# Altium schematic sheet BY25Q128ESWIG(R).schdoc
size 127 x 101 mm
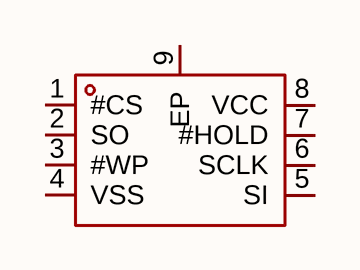
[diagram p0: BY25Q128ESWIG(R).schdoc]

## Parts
U?  by25q128eswig(r)  [DFN-8_L6.0-W5.0-P1.27-TL-EP4.0]  (value not drawn)

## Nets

Not connected (* = marked no-connect by the designer): U? 1(#CS) 2(SO) 3(#WP) 4(VSS) 5(SI) 6(SCLK) 7(#HOLD) 8(VCC) 9(EP)

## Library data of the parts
U? = by25q128eswig(r): Manufacturer: BOYAMICRO(博雅); AddInBom: yes; ModelId: 031cf1acb74a46ca8793eb7c9751e2bb; ModelTransform: 237.007,196.85,0,0,0,0,0,0,0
